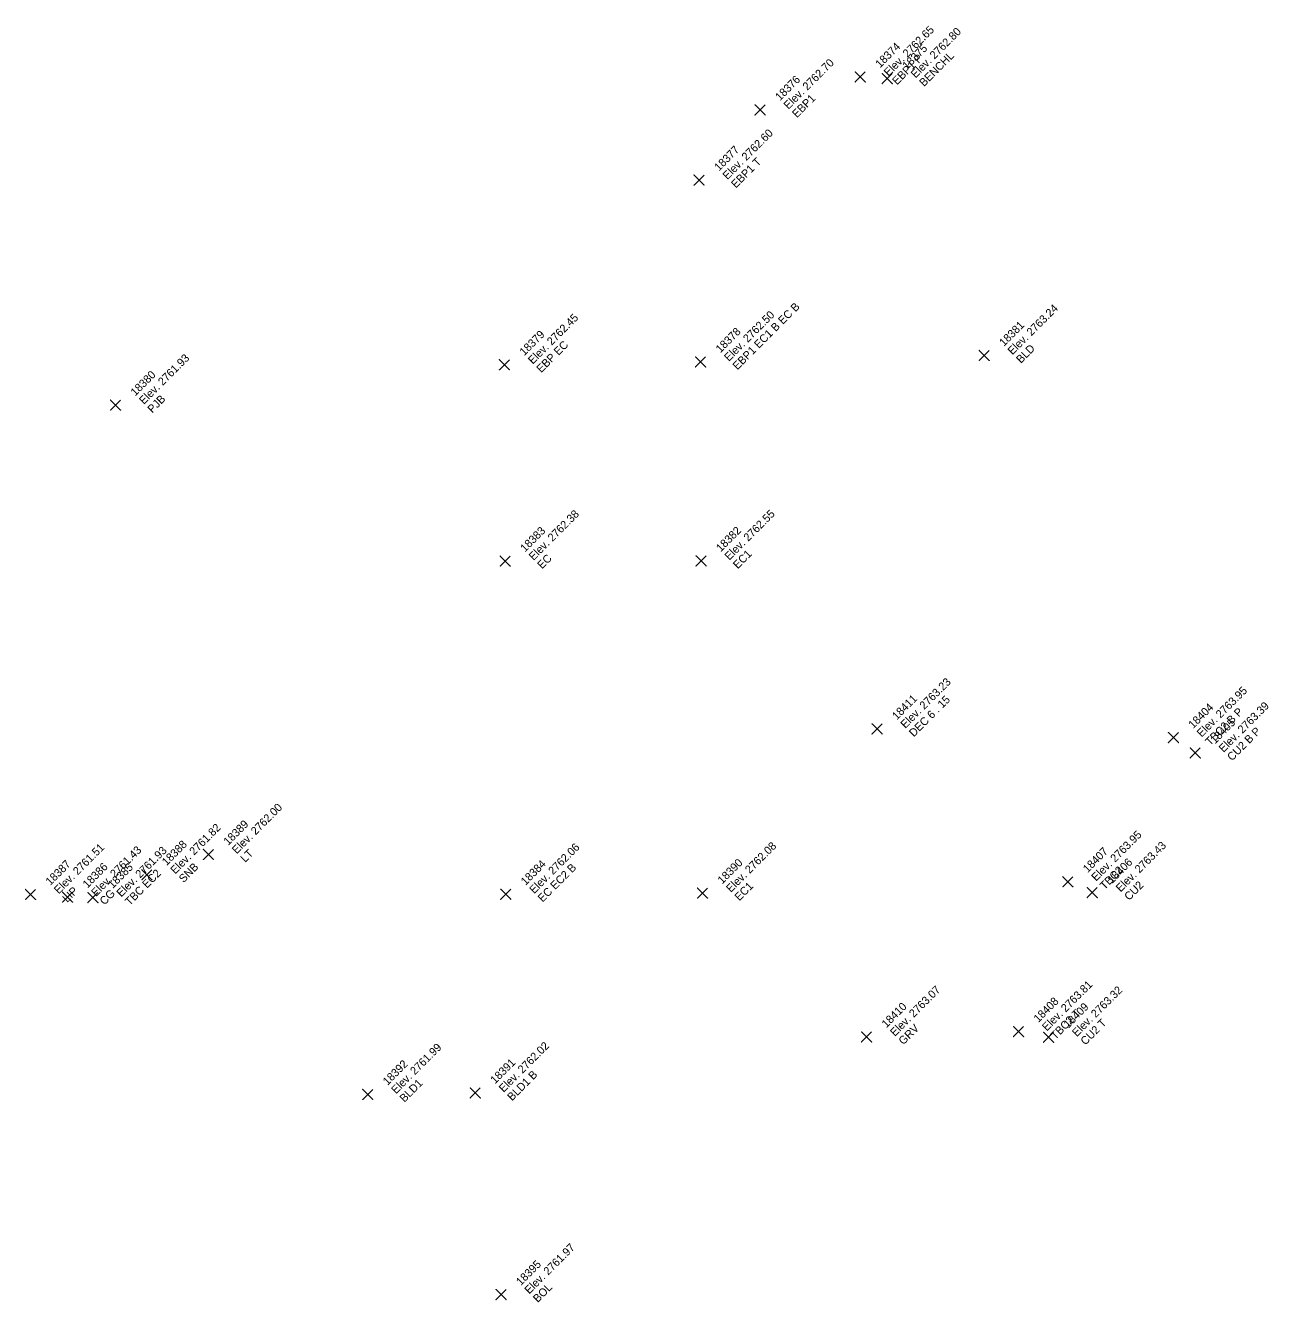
# Model space of a CAD drawing. Extents: x 2493999 to 2503109, y 700767 to 706646.
# Drawn here: x 2502305.39 to 2502342.69, y 701183.76 to 701222.05 of the extents above; entities that cross this region are included whole.
import ezdxf

# ---------------------------------------------------------------- set-up
doc = ezdxf.new("R2010")
doc.units = 0
doc.layers.add('ALG_CL_BLUE_Horiz', color=7, linetype='Continuous')
doc.layers.add('DES_SURFACE_Existing-Ground', color=7, linetype='Continuous')

msp = doc.modelspace()

# ---------------------------------------------------------------- linework, layer by layer
at = {"layer": 'ALG_CL_BLUE_Horiz'}
for points in [[(2502330.436, 701220.515), (2502330.286, 701220.665), (2502330.436, 701220.515), (2502330.286, 701220.365), (2502330.436, 701220.515), (2502330.586, 701220.365), (2502330.436, 701220.515), (2502330.586, 701220.665)], [(2502331.247, 701220.461), (2502331.097, 701220.611), (2502331.247, 701220.461), (2502331.097, 701220.311), (2502331.247, 701220.461), (2502331.397, 701220.311), (2502331.247, 701220.461), (2502331.397, 701220.611)], [(2502327.432, 701219.525), (2502327.282, 701219.675), (2502327.432, 701219.525), (2502327.282, 701219.375), (2502327.432, 701219.525), (2502327.582, 701219.375), (2502327.432, 701219.525), (2502327.582, 701219.675)], [(2502325.602, 701217.417), (2502325.452, 701217.567), (2502325.602, 701217.417), (2502325.452, 701217.267), (2502325.602, 701217.417), (2502325.752, 701217.267), (2502325.602, 701217.417), (2502325.752, 701217.567)], [(2502319.761, 701211.881), (2502319.611, 701212.031), (2502319.761, 701211.881), (2502319.611, 701211.731), (2502319.761, 701211.881), (2502319.911, 701211.731), (2502319.761, 701211.881), (2502319.911, 701212.031)], [(2502325.646, 701211.966), (2502325.496, 701212.116), (2502325.646, 701211.966), (2502325.496, 701211.816), (2502325.646, 701211.966), (2502325.796, 701211.816), (2502325.646, 701211.966), (2502325.796, 701212.116)], [(2502334.155, 701212.161), (2502334.005, 701212.311), (2502334.155, 701212.161), (2502334.005, 701212.011), (2502334.155, 701212.161), (2502334.305, 701212.011), (2502334.155, 701212.161), (2502334.305, 701212.311)], [(2502308.09, 701210.672), (2502307.94, 701210.822), (2502308.09, 701210.672), (2502307.94, 701210.522), (2502308.09, 701210.672), (2502308.24, 701210.522), (2502308.09, 701210.672), (2502308.24, 701210.822)], [(2502319.784, 701205.994), (2502319.634, 701206.144), (2502319.784, 701205.994), (2502319.634, 701205.844), (2502319.784, 701205.994), (2502319.934, 701205.844), (2502319.784, 701205.994), (2502319.934, 701206.144)], [(2502325.658, 701206), (2502325.508, 701206.15), (2502325.658, 701206), (2502325.508, 701205.85), (2502325.658, 701206), (2502325.808, 701205.85), (2502325.658, 701206), (2502325.808, 701206.15)], [(2502330.94, 701200.959), (2502330.79, 701201.109), (2502330.94, 701200.959), (2502330.79, 701200.809), (2502330.94, 701200.959), (2502331.09, 701200.809), (2502330.94, 701200.959), (2502331.09, 701201.109)], [(2502339.831, 701200.698), (2502339.681, 701200.848), (2502339.831, 701200.698), (2502339.681, 701200.548), (2502339.831, 701200.698), (2502339.981, 701200.548), (2502339.831, 701200.698), (2502339.981, 701200.848)], [(2502340.487, 701200.24), (2502340.337, 701200.39), (2502340.487, 701200.24), (2502340.337, 701200.09), (2502340.487, 701200.24), (2502340.637, 701200.09), (2502340.487, 701200.24), (2502340.637, 701200.39)], [(2502310.876, 701197.195), (2502310.726, 701197.345), (2502310.876, 701197.195), (2502310.726, 701197.045), (2502310.876, 701197.195), (2502311.026, 701197.045), (2502310.876, 701197.195), (2502311.026, 701197.345)], [(2502309.03, 701196.588), (2502308.88, 701196.738), (2502309.03, 701196.588), (2502308.88, 701196.438), (2502309.03, 701196.588), (2502309.18, 701196.438), (2502309.03, 701196.588), (2502309.18, 701196.738)], [(2502336.666, 701196.376), (2502336.516, 701196.526), (2502336.666, 701196.376), (2502336.516, 701196.226), (2502336.666, 701196.376), (2502336.816, 701196.226), (2502336.666, 701196.376), (2502336.816, 701196.526)], [(2502305.539, 701195.994), (2502305.389, 701196.144), (2502305.539, 701195.994), (2502305.389, 701195.844), (2502305.539, 701195.994), (2502305.689, 701195.844), (2502305.539, 701195.994), (2502305.689, 701196.144)], [(2502306.653, 701195.916), (2502306.503, 701196.066), (2502306.653, 701195.916), (2502306.503, 701195.766), (2502306.653, 701195.916), (2502306.803, 701195.766), (2502306.653, 701195.916), (2502306.803, 701196.066)], [(2502307.412, 701195.903), (2502307.262, 701196.053), (2502307.412, 701195.903), (2502307.262, 701195.753), (2502307.412, 701195.903), (2502307.562, 701195.753), (2502307.412, 701195.903), (2502307.562, 701196.053)], [(2502319.8, 701196.001), (2502319.65, 701196.151), (2502319.8, 701196.001), (2502319.65, 701195.851), (2502319.8, 701196.001), (2502319.95, 701195.851), (2502319.8, 701196.001), (2502319.95, 701196.151)], [(2502325.704, 701196.038), (2502325.554, 701196.188), (2502325.704, 701196.038), (2502325.554, 701195.888), (2502325.704, 701196.038), (2502325.854, 701195.888), (2502325.704, 701196.038), (2502325.854, 701196.188)], [(2502337.399, 701196.053), (2502337.249, 701196.203), (2502337.399, 701196.053), (2502337.249, 701195.903), (2502337.399, 701196.053), (2502337.549, 701195.903), (2502337.399, 701196.053), (2502337.549, 701196.203)], [(2502330.626, 701191.724), (2502330.476, 701191.874), (2502330.626, 701191.724), (2502330.476, 701191.574), (2502330.626, 701191.724), (2502330.776, 701191.574), (2502330.626, 701191.724), (2502330.776, 701191.874)], [(2502335.185, 701191.883), (2502335.035, 701192.033), (2502335.185, 701191.883), (2502335.035, 701191.733), (2502335.185, 701191.883), (2502335.335, 701191.733), (2502335.185, 701191.883), (2502335.335, 701192.033)], [(2502336.086, 701191.715), (2502335.936, 701191.865), (2502336.086, 701191.715), (2502335.936, 701191.565), (2502336.086, 701191.715), (2502336.236, 701191.565), (2502336.086, 701191.715), (2502336.236, 701191.865)], [(2502315.656, 701190), (2502315.506, 701190.15), (2502315.656, 701190), (2502315.506, 701189.85), (2502315.656, 701190), (2502315.806, 701189.85), (2502315.656, 701190), (2502315.806, 701190.15)], [(2502318.885, 701190.045), (2502318.735, 701190.195), (2502318.885, 701190.045), (2502318.735, 701189.895), (2502318.885, 701190.045), (2502319.035, 701189.895), (2502318.885, 701190.045), (2502319.035, 701190.195)], [(2502319.657, 701183.995), (2502319.507, 701184.145), (2502319.657, 701183.995), (2502319.507, 701183.845), (2502319.657, 701183.995), (2502319.807, 701183.845), (2502319.657, 701183.995), (2502319.807, 701184.145)]]:
    msp.add_lwpolyline(points, dxfattribs=at)

# ---------------------------------------------------------------- texts
at = {"layer": 'DES_SURFACE_Existing-Ground'}
for s, p in [('Elev. 2762.65', (2502331.285, 701220.515)), ('Elev. 2762.80', (2502332.096, 701220.461)), ('18374', (2502331.03, 701220.77)), ('EBP1 P', (2502331.539, 701220.26)), ('18375', (2502331.841, 701220.716)), ('BENCHL', (2502332.35, 701220.206)), ('Elev. 2762.70', (2502328.281, 701219.525)), ('18376', (2502328.026, 701219.78)), ('EBP1', (2502328.535, 701219.27)), ('Elev. 2762.60', (2502326.451, 701217.417)), ('18377', (2502326.196, 701217.672)), ('EBP1 T', (2502326.705, 701217.162)), ('Elev. 2762.50', (2502326.495, 701211.966)), ('EBP1 EC1 B EC B', (2502326.749, 701211.711)), ('Elev. 2763.24', (2502335.004, 701212.161)), ('Elev. 2762.45', (2502320.61, 701211.881)), ('18381', (2502334.749, 701212.416)), ('18379', (2502320.355, 701212.136)), ('18378', (2502326.24, 701212.221)), ('EBP EC', (2502320.864, 701211.626)), ('BLD', (2502335.258, 701211.906)), ('Elev. 2761.93', (2502308.939, 701210.672)), ('18380', (2502308.684, 701210.927)), ('PJB', (2502309.193, 701210.417)), ('Elev. 2762.38', (2502320.633, 701205.994)), ('Elev. 2762.55', (2502326.507, 701206)), ('18383', (2502320.378, 701206.249)), ('18382', (2502326.252, 701206.255)), ('EC1', (2502326.761, 701205.745)), ('EC', (2502320.887, 701205.739)), ('Elev. 2763.23', (2502331.789, 701200.959)), ('Elev. 2763.95', (2502340.68, 701200.698)), ('18411', (2502331.534, 701201.214)), ('DEC 6 . 15', (2502332.043, 701200.704)), ('18404', (2502340.425, 701200.953)), ('Elev. 2763.39', (2502341.336, 701200.24)), ('TBC2 B P', (2502340.934, 701200.443)), ('18405', (2502341.081, 701200.495)), ('CU2 B P', (2502341.59, 701199.985)), ('Elev. 2762.00', (2502311.725, 701197.195)), ('18389', (2502311.47, 701197.45)), ('Elev. 2761.82', (2502309.879, 701196.588)), ('Elev. 2763.95', (2502337.515, 701196.376)), ('Elev. 2761.51', (2502306.388, 701195.994)), ('Elev. 2761.43', (2502307.502, 701195.916)), ('Elev. 2761.93', (2502308.261, 701195.903)), ('18388', (2502309.624, 701196.843)), ('Elev. 2762.06', (2502320.649, 701196.001)), ('Elev. 2762.08', (2502326.553, 701196.038)), ('18407', (2502337.26, 701196.631)), ('Elev. 2763.43', (2502338.248, 701196.053)), ('18387', (2502306.133, 701196.249)), ('LT', (2502311.979, 701196.94)), ('18384', (2502320.394, 701196.256)), ('18390', (2502326.298, 701196.293)), ('18406', (2502337.993, 701196.308)), ('18386', (2502307.247, 701196.171)), ('18385', (2502308.006, 701196.158)), ('TBC EC2', (2502308.515, 701195.648)), ('SNB', (2502310.133, 701196.333)), ('EC EC2 B', (2502320.903, 701195.746)), ('TBC2', (2502337.769, 701196.121)), ('EC1', (2502326.807, 701195.783)), ('CU2', (2502338.502, 701195.798)), ('LIP', (2502306.642, 701195.739)), ('CG', (2502307.756, 701195.661)), ('Elev. 2763.07', (2502331.475, 701191.724)), ('Elev. 2763.81', (2502336.034, 701191.883)), ('Elev. 2763.32', (2502336.935, 701191.715)), ('18408', (2502335.779, 701192.138)), ('18410', (2502331.22, 701191.979)), ('TBC2 T', (2502336.288, 701191.628)), ('18409', (2502336.68, 701191.97)), ('GRV', (2502331.729, 701191.469)), ('CU2 T', (2502337.189, 701191.46)), ('Elev. 2761.99', (2502316.505, 701190)), ('Elev. 2762.02', (2502319.734, 701190.045)), ('18392', (2502316.25, 701190.255)), ('18391', (2502319.479, 701190.3)), ('BLD1 B', (2502319.988, 701189.79)), ('BLD1', (2502316.759, 701189.745)), ('Elev. 2761.97', (2502320.506, 701183.995)), ('18395', (2502320.251, 701184.25)), ('BOL', (2502320.76, 701183.74))]:
    msp.add_text(s, height=0.24, rotation=45, dxfattribs=at).set_placement(p)

doc.saveas('drawing.dxf')
